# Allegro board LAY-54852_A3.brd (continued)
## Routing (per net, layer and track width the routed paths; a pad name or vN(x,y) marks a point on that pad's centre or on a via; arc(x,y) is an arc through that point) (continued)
VRPI_3V3: length 26.4
  TOP w0.508: J1401.17 v1(108.51,73.84)
  BOTTOM w0.508: v1(86.85,77.34) 88.83,75.36 102.11,75.36 103.97,73.5 104.46,73.5 104.91,73.05 107.94,73.05 108.51,73.62 v1(108.51,73.84)
VSD2_3V3: length 40.7
  TOP w0.254: U1708.A1 130.26,43.85 D1003.1
  TOP w0.508: J1002.4 125.06,53.99 C1732.1 122.54,53.99 R1055.2 v1(122.37,54.88) ; v1(122.37,44.17) 120.29,42.08 120.29,38.83 122.58,36.54 125.57,36.54 TP1919.1 129.56,40.53 C1731.1 130.24,42.84 131.73,42.84 132.21,43.32 D1003.1
  BOTTOM w0.508: v1(122.37,54.88) 123.04,54.21 123.04,44.84 v1(122.37,44.17)
VSD_3V3: length 108.5
  TOP w0.203: v1(65.94,26.23) 65.71,26.47 U701.23
  TOP w0.254: U1708.A2 127.83,44.2 C1020.1
  TOP w0.381: v1(67.2,21.11) 67.2,24.97 v1(65.94,26.23)
  TOP w0.508: v1(118.9,45.52) 115.69,48.73 v1(108.03,48.73) ; v1(75.99,24.77) 75.36,24.14 75.36,20.52 v1(74.69,19.85) ; R1055.1 v1(120.25,54.16) ; v1(121.19,45.52) 126.91,45.52 127.71,44.72 C1020.1
  BOTTOM w0.381: C725.1 65.74,26.44 v1(65.94,26.23)
  BOTTOM w0.508: v1(118.9,45.52) v1(121.19,45.52) 121.46,45.79 121.46,52.94 v1(120.25,54.16) ; v1(67.2,21.11) 67.2,20.07 68.4,18.88 73.72,18.88 v1(74.69,19.85) ; v1(108.03,48.73) 108.51,48.73 110.88,46.36 110.88,38.14 108.27,35.52 101.75,35.52 95.25,29.02 94.44,29.02 92.96,27.54 92.96,26.98 91,25.03 76.25,25.03 v1(75.99,24.77)
VSYS_5V: length 69.7
  TOP w0.203: v1(63.55,35.12) 63.71,34.95 U701.53
  TOP w0.254: U701.56 61.66,34 v1(61.53,34.13) ; R906.1 42.66,34.97 42.51,34.82 U901.5
  TOP w0.381: R906.1 43.38,34.93 C902.1 v1(42.6,33.94)
  TOP w0.457: 134.97,28.91 131.96,28.91 R1783.1
  BOTTOM w0.381: v1(43.59,40.97) 42.6,39.98 v1(42.6,33.94)
  BOTTOM w1.27: 136.57,27.94 136.57,22.5 137.21,21.86 137.21,7.31 132.68,2.78 108.96,2.78
  vias: v1(32.01,21.94) v1(32.02,21.39) v1(32.03,20.87) v1(32.03,20.36) v1(37.33,43.99) v1(37.35,43.36) v1(37.96,43.99) v1(38,43.46) v1(56.76,38.78) v1(56.74,38.27) v1(56.91,41.01) v1(56.93,40.38) v1(57.54,41.01) v1(57.57,40.48) v1(63.01,26.23) v1(63.64,26.21) v1(65.36,34.98) v1(65.99,34.96) v1(69.53,30.3) v1(69.51,29.67) v1(107.58,3.58) v1(107.58,3.07) v1(107.58,2.48) v1(107.6,1.97) v1(136.47,30.07) v1(136.47,29.49) v1(136.49,28.92)
VTREF: length 2.9
  TOP w0.091: R1454.2 30.75,51.01 J1704.1
WDOG_B: length 224.3
  TOP w0.081: U101.H14 v1(90.99,52.71)
  TOP w0.091: v1(97.02,62.13) 97.02,62.6 95.58,64.04 95.58,65.2 91.5,69.28 70.46,69.28 70.14,69.59 60.98,69.59 57.9,72.68 v1(48.16,72.68) ; v1(54.62,58.47) 38.16,58.47 33.04,63.59 v1(33.04,63.97) ; v1(74.7,22.64) 74.78,22.72 74.78,23.41 TP916.1 73.23,23.62 R710.1 ; v1(31.99,57.06) 31.71,56.78 26.42,56.78 23.33,53.69 23.33,51.53 21.92,50.12 18.19,50.12 16.12,52.18 16.12,53.96 11.32,58.76 11.32,59.32 9.71,60.93 Q1407.1 9,62.38 7.34,62.38 6.72,61.76 Q1411.1 ; v1(42.91,72.68) 34.23,72.68 v1(33.41,71.85)
  BOTTOM w0.091: v1(31.99,57.06) 31.99,57.08 33.04,58.13 v1(33.04,63.97) 33.04,71.48 v1(33.41,71.85) ; v1(42.91,72.68) v1(48.16,72.68) ; v1(97.02,62.13) 96.4,61.51 96.4,57.01 95.77,56.38 95.77,55.42 92.11,51.75 91.95,51.75 v1(90.99,52.71) ; v1(54.62,58.47) 54.66,58.43 54.66,31.66 55.3,31.02 55.3,19.29 55.95,18.65 63.61,18.65 66.97,22 68,22 68.16,21.84 69.59,21.84 70.04,22.29 74.35,22.29 v1(74.7,22.64)
XIN_32K: length 6.2
  TOP w0.091: QZ701.2 58.51,28.21 58.81,28.51 C716.1
  TOP w0.104: U701.10 61.01,29.55 59.84,28.38 59.84,27.92 59.74,27.82 R720.1 59.34,28.51 C716.1
XOUT_32K: length 6.5
  TOP w0.104: QZ701.1 57.7,25.71 58.56,26.57 C717.1 59.34,27.28 R720.2 59.57,27.28 60.07,27.78 60.07,28.19 61.04,29.15 U701.11
XTALI_24M: length 14.3
  TOP w0.081: U101.A9 88.49,57.31 88.65,57.46 88.65,57.85 v1(88.51,57.99)
  TOP w0.091: v1(88.56,65.32) 88.56,65.32 88.17,65.7 87.75,65.7 TP410.1
  BOTTOM w0.081: 88.85,58.37 88.76,58.37 88.51,58.13 v1(88.51,57.99)
  BOTTOM w0.091: 91.04,62.68 90.03,63.7 90.03,64.89 89.86,65.06 88.82,65.06 v1(88.56,65.32) 88.46,65.42 R409.1 89.29,65.91 C404.1 ; 91.04,62.68 Y401.1 ; 91.04,62.68 91.01,62.68 90.24,61.92 90.24,61.74 89.42,60.92 89.42,58.95 88.85,58.37
XTALI_32K: length 7.2
  TOP w0.091: v1(86.53,57.28) 86.55,57.26 86.55,56.76 U101.A5
  BOTTOM w0.081: 86.85,58.1 86.85,57.6 v1(86.53,57.28)
  BOTTOM w0.102: R407.1 86.69,60.51 86.85,60.35 86.85,58.1 ; R407.1 86.69,62.47 R406.2 ; R407.1 86.71,62.04 TP407.1
XTALO_24M: length 12.4
  TOP w0.081: 88.39,58.37 88.17,58.16 88.17,57.63 88.25,57.55 88.25,56.45 U101.B9
  TOP w0.091: 88.39,58.37 88.48,58.46 88.48,58.59 v1(88.46,58.6)
  BOTTOM w0.091: C405.1 87.69,65.93 R409.2 87.71,65.51 Y401.3 89.91,63.32 89.91,61.72 89.18,60.99 89.18,59.04 88.74,58.6 v1(88.46,58.6)
XTALO_32K: length 10.6
  TOP w0.081: U101.B5 86.25,56.45 86.25,56.91
  TOP w0.091: 86.25,56.91 86.14,57.03 86.14,57.39 v1(86.53,57.78)
  TOP w0.102: R408.2 v1(83.98,62.08)
  BOTTOM w0.081: 86.34,58.37 86.53,58.18 v1(86.53,57.78)
  BOTTOM w0.091: v1(83.98,62.08) 83.98,60.73 86.34,58.37
  BOTTOM w0.102: v1(83.98,62.08) 83.42,62.08 C403.1 83.4,62.69 82.8,63.29 QZ401.1
N111682856: length 5.1
  TOP w0.254: S1501.2 39.39,62.19 C1507.1 39.39,65.34 38.75,65.97 R1504.1
N111682880: length 1.7
  TOP w0.381: R1505.1 24.88,77.8 D1501.C
N111682886: length 1.3
  TOP w0.254: R1506.1 33.82,77.8 D1502.C
N111683153: length 4.3
  TOP w0.254: R1511.2 45.87,64.97 C1508.1 44.69,63.14 S1501.1
N111686445: length 4.6
  TOP w0.254: R901.1 38.99,35.77 U901.8
N111686449: length 1
  TOP w0.254: C901.1 35.94,41.09 R901.2
N111686641: length 33.2
  TOP w0.381: R907.1 35.81,31.9 36.62,31.1 37.33,31.1 38.84,29.59 38.84,22.44 38.95,22.33
  TOP w0.508: D901.C 47.32,7.64 43.52,11.43 43.52,18.98 42.04,20.46 40.81,20.46 38.95,22.33
N111686683: length 2.1
  TOP w0.305: R907.2 37.97,33.82 U901.12
N111686689: length 16.1
  TOP w0.254: R906.2 44.71,34.97 44.96,34.72 44.96,31.58 44.71,31.32 42.82,31.32 v1(42.46,30.97) ; v1(36.54,33.27) 36.66,33.38 R910.1
  TOP w0.305: U901.11 36.73,34.32 R910.1
  BOTTOM w0.254: v1(36.54,33.27) 38.84,30.97 v1(42.46,30.97)
N111686749: length 10.3
  TOP w0.254: R911.1 42.76,36.12 41.97,35.32 U901.6 40.94,36 v1(41,36.06) ; R908.2 v1(35.75,37.55)
  BOTTOM w0.254: v1(35.75,37.55) 39.51,37.55 v1(41,36.06)
N112168459: length 4.2
  TOP w0.091: U1401.12 118.91,67.73 118.42,68.22 118.42,69.66 117.43,70.65 R1402.2
N112168530: length 2.9
  TOP w0.091: U1401.11 119.77,70.04 TP1402.1
N112168572: length 2.3
  TOP w0.091: R1409.2 119.77,64.44 U1401.1
N112168574: length 2.8
  TOP w0.091: U1401.10 120.27,70.4 TP1403.1
N112168590: length 2.2
  TOP w0.091: U1401.2 120.27,64.4 R1410.2
N112168603: length 2.5
  TOP w0.091: R1412.2 120.77,65.12 U1401.3
N112168605: length 3.5
  TOP w0.091: TP1404.1 120.77,69.08 U1401.9
N112168607: length 5.1
  TOP w0.091: D1401.C 124.03,64.87 R1420.2 121.27,65.81 U1401.4
N112179037: length 9.9
  TOP w0.091: J1401.37 133.91,74.38 133.3,73.77 v1(131.46,73.77)
  L3_PWR w0.114: J1710.2 128.35,72.21 129.91,73.77 v1(131.46,73.77)
N112179124: length 3.1
  TOP w0.091: J1401.36 v1(131.37,83.77)
  BOTTOM w0.091: v1(131.37,83.77) 131.27,83.67 R856.1
N112179125: length 37.2
  TOP w0.091: v1(130.04,78.99) 130.04,83.4 128.86,84.58 102.36,84.58 100.89,83.11 J1401.12
  BOTTOM w0.091: R855.1 130.06,78.97 v1(130.04,78.99)
N112179128: length 2.8
  TOP w0.091: J1401.16 v1(105.97,79.17)
  BOTTOM w0.091: v1(105.97,79.17) 105.96,79.18 R853.1
N112247759: length 6.5
  TOP w0.091: R811.2 104.84,65.5 C803.1 104.97,64.48 R804.2 105.38,63.81 105.38,62.36 105.92,61.82 U801.28
N112248110: length 5.2
  TOP w0.091: U801.32 106.76,59.82 105.48,58.54 105.48,57.58 R813.2 104.82,56.92 R823.2
N112248290: length 4.7
  TOP w0.091: R830.2 R824.2 R801.2 105.52,60.82 U801.30
N112248296: length 4.5
  TOP w0.091: R820.2 R828.2 R802.2 105.85,61.19 105.98,61.32 U801.29
N113364863: length 9.5
  TOP w0.091: R1444.1 59.68,65.66 J1405.6 54.45,65.66 54.16,65.37 54.16,63.97 54.48,63.65 J1405.8
N113365543: length 4.1
  TOP w0.091: J1405.3 49.23,67.69 R1446.1 49.13,68.9 R1440.2
N113365548: length 4.3
  TOP w0.091: R1441.2 49.15,65.48 R1447.1 50.13,65.46 50.33,65.66 J1405.5
N113409056: length 5.8
  TOP w0.091: R1426.1 22.77,82.34 SW1401.3 SW1401.4
N113409060: length 6.3
  TOP w0.091: R1427.1 36.66,81.72 36.04,82.34 SW1402.4 SW1402.3
N113524078: length 3.7
  TOP w0.102: R408.1 86.04,61.8 v1(86.04,61.53)
  BOTTOM w0.102: v1(86.04,61.53) 86.16,61.64 R407.2 85.54,62.06 C402.1 85.53,62.52 85.3,62.75 QZ401.2
N113527145: length 6.4
  TOP w0.104: U701.38 69.26,31.55 69.88,32.17 69.88,33.61 70.29,34.02 R701.2 R711.1
N113527381: length 5.1
  TOP w0.203: R718.1 R716.2 71.05,27.15 70.31,27.15 69.85,27.61 69.85,27.83 69.32,28.35 U701.30
N113528020: length 6.1
  TOP w0.104: U701.12 61.15,28.75 60.37,27.98 60.37,27.67 ; 59.67,25.46 58.68,24.47 R723.1
  TOP w0.109: 59.67,25.46 59.67,26.98 60.37,27.67
N113528254: length 5.3
  TOP w0.203: C728.1 60.65,33.3 61.19,32.75 U701.2
  TOP w0.254: C728.1 59.82,33.55 59.56,33.81 58.6,33.81 57.73,34.68 TP710.1
N113528336: length 3.7
  TOP w0.203: U701.1 61.39,33.15 60.86,33.68
  TOP w0.381: 60.86,33.68 60.78,33.76 60.78,34.56 60.64,34.7 ; 60.64,34.7 v1(60.67,34.72) ; 60.64,34.7 60.3,34.7 C730.1
  BOTTOM w0.381: v1(60.67,34.72) 60.16,35.23 R871.1
N114502549: length 1.6
  TOP w0.091: R1703.2 22.68,72 U1702.2
N114502556: length 2
  TOP w0.091: R1704.2 24.37,70.29 U1702.5
N114502597: length 2.1
  TOP w0.091: U1702.7 25.17,69.57 24.67,69.07 R1705.2
N114579559: length 2.6
  TOP w0.091: U801.1 107.93,58.72 107.62,58.41 106.83,58.41 R805.1
N114579565: length 2.1
  TOP w0.091: R807.1 107.55,58.12 107.92,58.12 108.43,58.63 U801.2
N114579571: length 1.7
  TOP w0.091: U801.3 108.93,58.47 R806.1
N114579577: length 1.5
  TOP w0.091: U801.4 109.43,58.56 109.14,58.28 R809.1
N114579583: length 1.4
  TOP w0.091: U801.5 109.93,57.91 R812.1
N114579589: length 1.7
  TOP w0.091: U801.6 110.43,58.42 R810.1
N114579595: length 25.9
  TOP w0.091: U801.7 110.93,58.64 111.4,58.17 112.84,58.17 v1(113.29,58.61)
  BOTTOM w0.091: v1(113.29,58.61) 113.29,58.66 114.4,59.78 114.4,73.42 113.12,74.7 113.12,78.17 114.58,79.63 R850.1
N114579601: length 24.9
  TOP w0.091: v1(113.24,59.14) 113.12,59.02 U801.8
  BOTTOM w0.091: v1(113.24,59.14) 114.19,60.09 114.19,72.99 109.49,77.68 R851.1
N114598355: length 1.8
  TOP w0.091: v1(113.24,59.68) 113.13,59.68 112.99,59.82 U801.9
  BOTTOM w0.091: v1(113.24,59.68) 113.32,59.68 113.46,59.82 R852.1
N114598565: length 2.5
  TOP w0.091: U801.10 113.28,60.32 114.14,59.46 R845.1
N114629076: length 3.1
  TOP w0.254: R703.2 R706.2 60.42,29.93 60.84,30.35 U701.8
N114629170: length 6.2
  TOP w0.112: R710.2 72.65,24.38 R705.2 71.34,24.63 68.87,27.1 U701.28
N114629402: length 2.2
  TOP w0.091: R818.1 113.48,60.82 U801.11
N114629754: length 6.1
  TOP w0.104: R707.2 69.65,33.78 69.65,32.27 69.33,31.95 U701.39
N114629773: length 6.7
  TOP w0.104: U701.40 69.31,32.35 69.42,32.46 69.42,33.89 71.54,36.02 71.54,36.73 R708.2
N114629886: length 7.6
  TOP w0.104: U701.42 68.56,33.78 70.99,36.2 70.99,38.3 R715.2
N114629887: length 7.2
  TOP w0.104: R714.2 71.26,37.51 71.26,36.12 69.19,34.05 69.19,32.86 69.08,32.75 U701.41
N114636326: length 4.3
  TOP w0.203: TP714.1 58.06,32.07 58.31,31.82 59.86,31.82 60.46,31.22 61.06,31.22 61.13,31.15 U701.6
N114797754: length 2
  TOP w0.091: R1423.1 82.02,75.06 81.03,76.05 D1402.4
N114797756: length 1.9
  TOP w0.091: R1424.1 81.03,81.09 D1402.3
N114797758: length 2.8
  TOP w0.091: D1402.1 79.53,75.16 79.87,74.82 R1425.1
N114798676: length 3.5
  TOP w0.091: R1439.2 76.75,73.86 R1435.1 78.25,72.35 Q1403.1
N114798680: length 2.8
  TOP w0.091: R1438.2 R1434.1 74.52,84.64 Q1401.1
N114800112: length 2.8
  TOP w0.091: R1429.2 87.7,72.76 R1433.1 86.01,72.22 Q1402.1
N114994571: length 3.2
  TOP w0.254: 50.81,38.18 U902.5
  TOP w0.381: R912.2 48.82,37.46 49.55,38.18 50.81,38.18
N114994603: length 2.8
  TOP w0.254: U902.2 52.01,41.12 52.07,41.19 R915.2 52.08,41.6 R213.2
N114997192: length 2.1
  TOP w0.254: R913.1 50.41,36.68 51.51,37.78 U902.6
N114999418: length 1.2
  TOP w0.381: D902.A R914.2
N115302368: length 2.4
  TOP w0.091: R839.1 129.44,69.39 130.14,70.09 U803.13
N115329910: length 3
  TOP w0.091: R854.2 105.97,73.43 J1401.15
N115331791: length 9.6
  TOP w0.091: J1405.2 54.5,69.7 54.24,69.44 54.24,67.95 54.5,67.69 J1405.4 58.43,67.69 59.31,66.82 R1442.1
N115508226: length 1.9
  TOP w0.091: U804.13 102.83,70.93 103.25,70.51 R841.1
N115508248: length 2.1
  TOP w0.102: U805.13 113.37,70.41 R840.1
N115511669: length 2.5
  TOP w0.091: U801.18 110.93,65.05 R829.1
N115511689: length 2.3
  TOP w0.091: U801.19 110.43,65.57 R833.1
N115511709: length 2.1
  TOP w0.091: R832.1 109.93,66.08 U801.20
N115511729: length 2.2
  TOP w0.091: R835.1 109.43,65.74 U801.21
N115511749: length 2.4
  TOP w0.091: R858.1 108.93,65.21 U801.22
N115511769: length 2.7
  TOP w0.091: R836.1 106.97,65.92 108.43,64.46 U801.23
N115511789: length 3
  TOP w0.091: R837.1 106.15,66.17 107.93,64.39 U801.24
N115511922: length 2.1
  TOP w0.091: U801.13 113.74,61.82 R821.1
N115511942: length 2.3
  TOP w0.091: U801.14 113.22,62.32 R825.1
N115511962: length 4.2
  TOP w0.091: v1(114.9,64.58) 114.45,64.13 114.25,64.13 112.95,62.82 U801.15
  BOTTOM w0.091: v1(114.9,64.58) 115.02,64.47 R860.1
N115511982: length 2.9
  TOP w0.091: R826.1 112.98,64.11 112.98,63.79 112.51,63.32 U801.16
N115512059: length 2.7
  TOP w0.091: R831.1 111.43,64.53 U801.17
N115512397: length 1.9
  TOP w0.091: U801.12 113.26,61.32 113.39,61.19 R822.1
N115575393: length 5.1
  TOP w0.091: U101.A3 85.49,57.39 85.05,57.84 85.05,60.42 84.44,61.03 R303.1
N115646354: length 3.9
  TOP w0.508: D1704.A 3.62,12.34 U1410.5 v1(6.09,12.34)
  BOTTOM w0.381: C1727.1 5.82,12.08 v1(6.09,12.34)
N115646421: length 5.4
  TOP w0.254: U1706.9 11.5,20.11 C1729.1
  TOP w0.508: L1703.2 11.95,17.01 C1728.1 11.95,19.62 C1729.1
N115646547: length 1.9
  TOP w0.381: U1410.4 v1(6.29,14.24)
  BOTTOM w0.381: C1730.1 5.82,14.24 v1(6.29,14.24)
N115646842: length 5.5
  TOP w0.254: U1706.4 9,19.85 C1416.1
  TOP w0.508: L1704.2 9.61,17.64 C1415.1 8.76,18.5 C1416.1
N115647748: length 3.7
  TOP w0.091: TP1429.1 20.53,30.06 18.48,30.06 18.28,29.87 U1706.29
N115647777: length 4.4
  TOP w0.091: TP1951.1 17.03,34.78 U1706.32
N115647791: length 4.1
  TOP w0.091: U1706.33 15,34.96 TP1952.1
N115647810: length 3.7
  TOP w0.091: TP1413.1 14.5,35.79 U1706.34
N115647904: length 1
  TOP w0.091: R1729.1 12.58,40.9 D1403.A
N115647959: length 1.5
  TOP w0.091: R1730.1 6.95,40.32 D1404.A
N115647999: length 3.7
  TOP w0.091: U1706.40 11.5,35.81 TP1414.1
N115648034: length 3.4
  TOP w0.091: TP1415.1 11,36.53 U1706.41
N115648083: length 3.5
  TOP w0.091: TP1416.1 9.78,36.44 9.78,34.62 10,34.39 U1706.43
N115648105: length 3.8
  TOP w0.091: TP1417.1 9.5,35.49 U1706.44
N115648131: length 4.1
  TOP w0.091: U1706.45 9,34.77 TP1418.1
N115648181: length 4.9
  TOP w0.091: TP1419.1 6.56,36 7.47,36 8.5,34.96 U1706.46
N115648263: length 1
  TOP w0.091: D1406.A 9.73,40.95 R1421.1
N115648354: length 1.7
  TOP w0.381: D1405.A 3.76,53.36 4.41,52.71 4.41,51.96 R1733.1
N115648363: length 4
  TOP w0.091: U1706.14 14,21.02 C1431.1 15.6,19.43 R1737.2
N115648415: length 2.3
  TOP w0.091: U1706.6 10,19.6 R1738.1
N115648419: length 3.8
  TOP w0.091: U1706.55 3.03,28.37 TP1420.1
N115648439: length 3.1
  TOP w0.091: U1405.1 4.67,46.16 R1422.1 5.86,46.3 R1734.2
N115648441: length 5.9
  TOP w0.091: R1735.2 R1428.1 ; R1735.2 2.97,40.14 3.14,39.97 3.14,38.14 TP1431.1 ; R1735.2 2.62,40.9 2.77,41.05 U1405.4
N115648443: length 6
  TOP w0.091: R1736.2 R1740.1 ; R1736.2 3.82,41.66 U1405.5 ; R1736.2 3.48,40.14 3.39,40.04 3.39,38.23 TP1432.1
N115648445: length 3.9
  TOP w0.091: U1706.57 3.25,27.37 TP1421.1
N115648473: length 4.2
  TOP w0.091: U1706.58 3.97,26.87 TP1422.1
N115648499: length 4.4
  TOP w0.091: TP1423.1 4.69,26.37 U1706.59
N115648584: length 5.6
  TOP w0.091: U1405.3 2.77,46.29 R1739.1 3.99,46.31 4.73,47.05 R1422.2 4.81,47.07 TP1430.1
N115648905: length 1.8
  TOP w0.091: U1406.7 13.47,61.29 R1430.1
N115648976: length 2.2
  TOP w0.091: R1741.1 14.62,62.29 U1406.5
N115649042: length 1.7
  TOP w0.091: U1406.2 19.74,61.29 R1743.1
N115649073: length 4.2
  TOP w0.254: 14.97,67.06 R1742.2 14.95,65.09 R1744.2 ; 14.97,67.06 14.88,66.97 U1407.1 ; 14.97,67.06 Q1404.3
N115649242: length 2.6
  TOP w0.381: R1467.2 4.56,64.18 3.75,64.18 D1412.A
N115649244: length 4
  TOP w0.152: D1413.A 4.26,66.13 5.37,67.25 5.37,68.49 R1748.2
N115649263: length 2.5
  TOP w0.254: R1750.1 18.3,66.45 R1749.2 16.92,66.45 Q1404.1
N115649426: length 1.1
  TOP w0.254: R1464.2 4.78,49.94 D1411.A
N115649428: length 2
  TOP w0.254: R1465.2 5.65,56.33 3.75,56.33 D1410.A
N115649511: length 5.4
  TOP w0.254: R1751.2 13.66,70.46 R1753.1 13.64,69.33 R1755.1 14.17,69.33 14.56,68.94 14.56,67.92 14.11,67.47 U1407.2
N115649521: length 9.6
  TOP w0.091: R1755.2 11.69,69.33 10.28,67.93 8.13,67.93 7.78,68.28 6.06,68.28 5.8,68.03 R1752.1
  TOP w0.254: U1407.4 12.89,68.19 12.84,68.25 12.84,68.75 12.89,68.81 R1755.2
N115650186: length 2.6
  TOP w0.091: R1486.2 R1487.2 21.46,53.21 U1409.22
N115650188: length 3.3
  TOP w0.091: R1490.1 17.05,56.33 R1485.2 17.06,55.25 U1409.18
N115650272: length 1.7
  TOP w0.091: U1409.5 24.73,57.25 TP1424.1
N115650294: length 2
  TOP w0.091: TP1425.1 24.01,57.75 U1409.6
N115650321: length 2.9
  TOP w0.091: TP1426.1 24.21,59.16 23.45,59.16 22.74,58.46 U1409.7
N115650337: length 3.6
  TOP w0.091: Q1406.3 30.97,54.17 R1454.1 30.89,52.16 C1449.1
N115650366: length 2.3
  TOP w0.091: U1409.8 21.96,58.91 22.85,59.8 TP1427.1
N115650410: length 18.5
  TOP w0.091: v1(29.9,50.84) 29.9,51.32 C1449.2 29.29,51.42 29.07,51.63 29.07,51.86 28.77,52.16 R1449.1 28.42,52.74 28.57,52.89 29.22,52.89 29.7,53.37 29.7,54.83 29.39,55.13 Q1406.1 27.8,55.13 R1756.2 ; C1448.2 v1(31.87,42.32)
  BOTTOM w0.091: v1(31.87,42.32) 31.87,48.86 v1(29.9,50.84)
N115650590: length 3.6
  TOP w0.091: TP1428.1 17.51,56.89 17.51,56.16 17.92,55.75 U1409.17
N115650809: length 2.3
  TOP w0.091: R1450.2 10.32,64.86 R1455.2 10.32,63.62 Q1407.3
N115650811: length 2.5
  TOP w0.091: R1457.2 23.79,63.92 R1451.2 22.69,64.92 Q1408.3
N115650813: length 3.5
  TOP w0.091: Q1409.3 19.64,19.68 R1452.2 18.59,21.24 R1456.2
N115650815: length 1
  TOP w0.254: D1415.A 3.76,58.97 R1453.2
N115650891: length 2.8
  TOP w0.091: R1461.1 24.01,41.03 D1407.C
N115651044: length 9.1
  TOP w0.254: D1415.C 3.27,60.03 6.13,60.03 R1458.2
  TOP w0.305: R1458.2 6.71,59.94 Q1410.3 9.96,59.94 R1816.2
N115651255: length 4.9
  TOP w0.254: R1468.2 4.84,62.91 5.52,63.58 Q1411.3
  TOP w0.381: R1468.2 4.79,61.88 3.75,61.88 D1414.A
N115651302: length 3.2
  TOP w0.091: R1462.1 26.94,50.92 J1704.7
N115651381: length 3.2
  TOP w0.091: J1704.9 25.67,51.01 R1463.1
N115688375: length 9.4
  TOP w0.091: R1057.2 136.39,46.12 130.1,46.12 129.42,45.45 U1708.B2
N115740207: length 35.6
  TOP w0.091: R1758.2 49.71,22.04 R305.2 49.2,22.05 v1(49.1,21.95) 48.72,21.95 U302.A3 ; Q301.3 73.48,17.02 v1(73.41,16.94)
  BOTTOM w0.091: v1(49.1,21.95) 49.1,21.59 57.99,12.7 71.88,12.7 73.41,14.23 v1(73.41,16.94)
N115740283: length 2.9
  TOP w0.254: SW301.3 70.04,5.95 R358.2 R353.2
N115740287: length 2.7
  TOP w0.254: R352.1 R356.1 69.71,3.78 SW301.2
N115740320: length 3
  TOP w0.254: R354.2 R359.2 65.8,6.99 SW301.6
N115740338: length 3.2
  TOP w0.254: SW301.5 65.64,3.35 R357.1 R355.1
N115740452: length 8.7
  TOP w0.254: R1760.2 71.39,17.54 R1761.1 71.9,17.54 72.27,17.17 72.27,15.54 71.94,15.22 C304.1 72.7,14.4 Q301.1 74.44,14.1 D301.A
N115740524: length 1.1
  TOP w0.091: TP305.1 70.65,11.76 U303.C3
N115740681: length 27.3
  TOP w0.091: R1764.2 67.72,9.04 64.16,9.04 62.15,11.05 62.15,14.17 v1(61.68,14.64) ; Q302.3 52.37,22.92 R1762.2 v1(51.7,21.71)
  BOTTOM w0.091: v1(51.7,21.71) 52.13,21.29 52.13,20.26 57.74,14.64 v1(61.68,14.64)
N115740897: length 1.8
  TOP w0.091: R313.1 66.82,15.09 67.21,15.09 67.44,14.86 U301.5
N115742694: length 3.3
  TOP w0.305: R1766.2 24.87,36.38 25.08,36.16 25.08,35.99 25.41,35.65 R1772.1 25.76,35.13 25.58,34.95 U404.4
N115742746: length 5.2
  TOP w0.305: D302.C 27.96,30.27 R360.2 27.84,29.98 R1769.2 26.93,29.99 R1771.1 25.86,30.59 25.58,30.87 U404.3
N115743253: length 2.7
  TOP w0.203: C407.1 23.66,13.9 U402.A6
N115743279: length 2
  TOP w0.091: C409.1 26.85,15.5 26.71,15.64 U402.A3
N115743338: length 2.3
  TOP w0.091: U402.A2 27.11,15.21 28.03,14.29 R412.2
N115743354: length 7.7
  TOP w0.091: U402.E1 29.13,17.35 29.33,17.15 R413.2 30.32,16.82 30.41,16.73 31.88,16.73 32.25,16.36 32.25,15.43 31.77,14.95 R434.2
N115743625: length 8.2
  TOP w0.381: D402.C 29.34,28.99 D401.C 29.4,32.82 C414.1 29.69,34.71 U405.2
N115744998: length 1.4
  TOP w0.091: U411.C3 34.34,20.46 TP1932.1
N115747363: length 2.2
  TOP w0.091: U1712.14 92.57,30.62 92.95,30.99 R1780.2
N115747381: length 2.2
  TOP w0.091: R503.2 92.95,29.85 92.57,30.22 U1712.13
N115751791:
  vias: v1(133.55,34.42) v1(134.06,34.42) v1(134.57,34.42)
N115751937: length 5
  TOP w0.254: U1710.3 132.04,34.85 131.22,35.68 C1749.2 131.2,36.37 R902.2 128.88,36.37 R1782.1
N115752033: length 2
  TOP w0.091: U1710.6 131.19,31.25 R1783.2
N115752037: length 2.7
  TOP w0.254: C1753.1 130.53,33.7 U1710.4
N115752085: length 1.8
  TOP w0.091: U1710.7 132.04,31.28 132.09,31.23 TP901.1
N115752389: length 1.8
  TOP w0.091: U904.2 128.87,26.02 R1784.2
N115752394: length 3.4
  TOP w0.091: R946.1 130.91,22.17 130.33,22.74 129.48,22.74 128.87,23.36 U904.10
N115752439: length 1.5
  TOP w0.091: U904.3 128.47,26.72 R1785.2
N115752462: length 2.8
  TOP w0.091: U904.9 128.47,23.25 129.19,22.52 129.73,22.52 R947.1
N115752527: length 1.8
  TOP w0.091: R1786.2 128.07,26.16 U904.4
N115752535: length 2.2
  TOP w0.091: U904.8 128.07,23.11 R948.1
N115752568: length 2
  TOP w0.091: U904.5 127.67,25.47 R909.2
N115752570: length 1.9
  TOP w0.091: U904.7 127.67,22.46 R949.1
N115753009: length 1.8
  TOP w0.091: D1705.A 133.46,19.29 133.8,19.64 R1790.1
N115753214: length 1
  TOP w0.091: D1706.A 131.14,18.34 R1791.1
N115753489: length 3.8
  TOP w0.091: Q901.3 119.94,21.25 120.38,20.81 120.47,20.81 120.88,20.4 R918.2 120.07,19.16 120.06,19.14 R919.2
N115753655: length 3
  TOP w0.381: R958.1 121.04,23.39 120.9,23.24 Q901.1 120.59,24.65 R959.1
N115753665: length 5.4
  TOP w0.091: J1707.62 118.1,15.38 116.17,17.32 R932.1
N115754842: length 3
  TOP w0.091: R1448.1 49.17,63.65 J1405.7
N115756645: length 17.2
  TOP w0.076: 104.27,29.07 104.27,28.58 U1709.E3
  TOP w0.081: 104.27,29.07 104.27,30.11 103.85,30.54 103.85,30.71
  TOP w0.091: v1(103.85,33.54) 103.85,30.71 ; R1204.2 v1(113.42,37.05)
  BOTTOM w0.091: v1(113.42,37.05) 113.15,37.05 109.63,33.54 v1(103.85,33.54)
N115756807: length 2
  TOP w0.203: U1709.G7 102.31,29.54 102.31,30.68 R1209.2
N115757278: length 2.4
  TOP w0.091: U1202.4 113.41,32.23 R1222.1 113.42,33.28 R1219.2
N115782425: length 5.5
  TOP w0.254: U1306.5 11.88,75.39 C1323.1
  TOP w0.305: R1814.1 10.83,73.24 C1321.1 ; C1321.1 10.89,73.21 C1322.1 11.88,73.23 C1323.1 ; C1321.1 R1329.1
N115782532: length 4.4
  TOP w0.254: U1306.4 9.07,75.41 8.69,75.03 R1330.1 R1329.2 C1321.2
N115782544: length 1.6
  TOP w0.254: R1333.2 9.86,78.13 U1306.3
N115782790: length 2.8
  TOP w0.091: R1302.1 2.75,5.86 3.89,6.99 U1301.1
N115782792: length 169.1
  TOP w0.091: v1(73,1.73) 73.06,1.67 R1303.2 ; U1307.2 18.77,78.58 16.88,80.47 14.36,80.47 v1(12.47,82.36) ; R1302.2 2.38,6.61 v1(2.44,6.55)
  BOTTOM w0.091: v1(12.47,82.36) 7.19,77.08 7.19,70.9 2.86,66.57 2.86,26.09 5.54,23.41 5.54,15.73 2.86,13.05 2.86,7.81 2.34,7.28 2.34,6.66 v1(2.44,6.55) 2.85,6.15 5.11,6.15 8.43,2.83 52.66,2.83 53.87,4.04 63.17,4.04 64.57,2.65 72.08,2.65 v1(73,1.73)
N115782811: length 243.2
  TOP w0.091: R1327.1 71.69,79.97 71.21,80.46 71.21,82.92 69.39,84.74 22.85,84.74 v1(22.04,83.93) 21.88,83.77 4.07,83.77 1.47,81.17 1.47,79.84 1.69,79.62 R1326.1 2.45,79.62 v1(2.46,79.62) ; R1324.1 1.67,9.67 v1(2.03,10.03) 2.9,10.9 3.71,10.9 v1(3.75,10.86) ; R1325.1 v1(76.67,12.29) ; v1(21.33,81.67) 20.81,81.15 U1309.4
  BOTTOM w0.091: v1(21.33,81.67) 21.33,83.22 v1(22.04,83.93) ; v1(76.67,12.29) 74.19,9.82 74.19,8.28 70.77,4.86 49.51,4.86 48.29,6.08 36.73,6.08 34.28,3.64 11.5,3.64 8.23,6.91 5.87,6.91 3.75,9.03 v1(3.75,10.86) ; v1(2.03,10.03) 2.64,10.64 2.64,13.14 5.28,15.78 5.28,22.76 2.64,25.4 2.64,67.31 6.35,71.02 6.35,73.41 3.24,76.51 3.24,78.91 2.53,79.62 v1(2.46,79.62)
N115782815: length 3
  TOP w0.091: U1301.2 3.89,8.83 3.34,9.37 2.64,9.37 1.76,8.5 R1324.2
N115783013: length 5.1
  TOP w0.091: R1303.1 74,6.28 74.73,7.01 U1302.1
N115783041: length 4.5
  TOP w0.091: R1325.2 75.92,10.82 75.29,10.19 74.37,10.19 74.24,10.06 74.24,9.42 74.73,8.94 U1302.2
N115783217: length 2.5
  TOP w0.091: U1304.1 3.89,77.77 3.52,77.4 R1318.1
N115783219: length 106.4
  TOP w0.091: v1(2.15,81.12) 2.08,81.19 2.08,81.35 4.2,83.47 22.15,83.47 23.05,84.37 69.31,84.37 70.93,82.75 70.93,78.07 71.99,77.01 R1322.2 ; U1308.2 19.3,69.22 19.09,69 17.43,69 17.13,69.31 17.13,70.49 16.45,71.17 8.61,71.17 7.93,71.85 7.85,71.85 4.19,75.51 v1(1.9,75.51) 1.9,75.51 R1318.2
  BOTTOM w0.091: v1(2.15,81.12) 1.9,80.87 v1(1.9,75.51)
N115783240: length 2.5
  TOP w0.091: U1304.2 3.89,79.66 3.17,80.37 R1326.2
N115783428: length 2.9
  TOP w0.091: U1305.1 74.73,77.82 74.16,77.26 73.43,77.26 72.92,77.76 R1322.1
N115783445: length 2.9
  TOP w0.254: R1327.2 73.67,80.72 74.73,79.66 U1305.2
N115785368: length 2.2
  TOP w0.091: R601.2 43.75,54.94 SW601.2
N115785370: length 2.2
  TOP w0.091: SW601.4 45.87,53.59 R602.2
N115785372: length 2.2
  TOP w0.091: SW601.6 45.8,52.32 R603.2
N115785374: length 2.3
  TOP w0.091: R604.2 45.72,51.05 SW601.8
N115788648: length 3.5
  TOP w0.091: R613.2 5.53,70.02 3.72,68.21 D601.A
N115837191: length 5.7
  TOP w0.081: U501.K5 104.24,40.15 102.38,40.15 101.87,39.64
  TOP w0.091: TP504.1 101.81,39.57 101.87,39.64
N115863629: length 3.9
  TOP w0.091: U1712.39 85.83,29.82 85.73,29.73 85.73,28.61 84.79,27.66 84.76,27.66 R508.1
N115865392: length 5.2
  TOP w0.081: 106.17,29.07 105.27,29.07 U1709.F2
  TOP w0.102: R1795.2 106.31,31.4 106.31,29.21 106.17,29.07
N115871876: length 29.9
  TOP w0.152: 105.98,30.59 105.98,29.46 105.84,29.32 U1709.G1
  TOP w0.203: R1203.2 99.53,18.94 96.46,22.01 96.46,30.06 101,34.6 104.63,34.6 106.16,33.07 106.16,31.87 105.98,31.69 105.98,30.59
N115938225: length 2.3
  TOP w0.076: v1(106.35,26.64) 105.93,27.07 105.28,27.07 U1709.C2
  TOP w0.203: v1(105.34,25.74) 105.34,25.81 105.02,26.13 U1709.A2
N115938370: length 3
  TOP w0.076: U1709.B4 103.77,26.58 103.77,25.87
  TOP w0.091: 104.01,25.15 104.01,25.09
  TOP w0.102: 103.77,25.87 103.77,25.39 104.01,25.15
  TOP w0.152: R1800.1 104.35,24.75 104.01,25.09
N115938505: length 10.8
  TOP w0.076: 102.29,28.08 102.61,28.08 102.87,27.82 U1709.D6
  TOP w0.081: 102.32,27.57 102.32,27.58 102.77,27.58 U1709.C6
  TOP w0.152: 102.29,28.08 102.17,28.2 102.02,28.2 ; v1(101.54,27.49) 101.62,27.57 102.32,27.57 ; U1709.G2 105.12,29.32 v1(105.58,29.78) ; U1709.G4 103.97,29.37 103.97,29.84 v1(103.82,29.99)
  TOP w0.203: 101.18,28.49 101.72,28.49 102.02,28.2
  TOP w0.254: L1201.2 100.79,27.03 101.06,27.03 101.51,27.49 v1(101.54,27.49)
  TOP w0.508: L1201.2 100.49,27.6 100.51,27.62 C1209.1 101.18,28.49
  BOTTOM w0.254: C1765.1 103.93,29.88 v1(103.82,29.99) ; C1207.1 106.35,29.78 v1(105.58,29.78)
N115954867: length 1.3
  TOP w0.203: R1798.1 102.33,20.43 C1769.2
N115954870: length 1.3
  TOP w0.203: R1801.1 105.71,20.29 C1770.2
N115959933: length 7.2
  TOP w0.076: U1709.C5 103.28,27.08 102.25,27.08 101.79,26.61 101.65,26.61
  TOP w0.152: 101.65,26.61 100.66,25.63 99.38,25.63 97.75,24 C1210.1
N115991118: length 11.5
  TOP w0.091: U904.12 131.99,24.62 R954.1 133.32,25.5 134.72,26.89 R1813.2 134.73,27.05 R953.2 135.58,26.06 135.24,25.72 Q902.3
N116057568: length 4.9
  TOP w0.081: 101.42,29.59 102.19,28.82 U1709.F7
  TOP w0.091: TP1953.1 99.85,30.86 100.78,30.86 101.22,30.43 101.22,29.79 101.42,29.59
N116084647: length 2.6
  TOP w0.091: U1713.5 12.11,49.92 R1718.1
N116084649: length 1.9
  TOP w0.091: U1713.8 9.57,49.92 8.91,50.58 R1723.1
N116084651: length 2.8
  TOP w0.091: U1713.4 11.87,49.31 12.71,50.15 R1717.1
N116084659: length 3.3
  TOP w0.091: U1713.9 8.96,49.31 7.8,50.46 R1724.1
N116084661: length 4.4
  TOP w0.091: U1713.1 11.61,48.11 12.51,47.2 12.51,45.91 13.12,45.3 R1719.1
N116086427: length 1.5
  TOP w0.091: R1817.2 10.78,46.19 U1713.15
N116086430: length 1.7
  TOP w0.091: R1818.2 10.38,46.85 U1713.14
N116086433: length 2.5
  TOP w0.091: U1713.13 9.98,47.24 9.7,46.96 8.89,46.96 8.51,46.59 R1819.2
N116086500: length 3.4
  TOP w0.091: R1820.2 7.54,46.05 9.6,48.11 U1713.12
N116087925: length 1.7
  TOP w0.091: U1713.16 11.18,46.66 R1821.1
N116088365: length 2.1
  TOP w0.091: R1720.1 11.61,50.52 11.02,50.52 10.78,50.28 U1713.6
N116088374: length 1.5
  TOP w0.091: U1713.7 10.38,50.42 R1721.1
N116165116: length 7.6
  TOP w0.091: R956.1 115.1,19.14 R957.1 115.43,19.14 115.62,18.94 115.62,17.34 117.6,15.36 J1707.64
N116167004: length 6.8
  BOTTOM w0.203: U1004.15 38.73,52.04 C1024.1
  BOTTOM w0.508: C1024.1 37.91,53.94 R1083.2 35.34,53.94 C1023.1
N116167167: length 1.4
  BOTTOM w0.381: R1072.1 42.16,55.43 D1012.C
N116167227: length 6.4
  BOTTOM w0.381: U1004.16 40.17,53.66 37.78,56.05 R1082.2 37.78,57.01 C1022.1
N116167406: length 2.5
  BOTTOM w0.203: R1077.2 43.97,52.54 U1004.1
N116167434: length 3
  BOTTOM w0.203: U1004.2 45.35,52.04 R1073.2 R1080.2
N116167436: length 17
  BOTTOM w0.203: R1081.2 35.46,46.97 36.43,46 44.9,46 45.47,46.57 R1074.2 45.01,48.92 45.01,50.04 44.52,50.54 U1004.5
N116167463: length 6.9
  BOTTOM w0.203: R1085.1 R1076.2 37.42,48.96 R1084.2 ; R1084.2 38.41,48.96 38.81,49.37 38.81,50.35 39,50.54 U1004.12 ; R1084.2 38.21,48.05 TP1020.1
N116167513: length 2.2
  BOTTOM w0.203: R1078.2 44.79,51.54 U1004.3
N116167550: length 2.8
  BOTTOM w0.203: U1004.4 44.49,51.04 45.47,50.05 R1079.2
N116167586: length 2.1
  BOTTOM w0.203: TP1015.1 43.57,47.02 U1004.8
N116167598: length 2.4
  BOTTOM w0.203: TP1016.1 40.17,47.46 U1004.9
N116167606: length 3.3
  BOTTOM w0.203: TP1017.1 39.47,46.91 39.47,49.29 39.73,49.54 U1004.10
N116167616: length 4.2
  BOTTOM w0.203: TP1018.1 39.14,47.67 39.14,49.5 39.68,50.04 U1004.11
N116227167: length 2.1
  TOP w0.091: J1710.1 124.84,71.31 R745.1
N116260997: length 6.8
  TOP w0.091: v1(117.07,73.24) 117.07,72.64 TP1954.1
  BOTTOM w0.091: U915.C1 116.36,76.91 R863.2 118.15,75.11 117.07,74.03 v1(117.07,73.24)
N116323997: length 18.2
  BOTTOM w0.381: D1011.C 47.14,60.13 44.67,62.59 40.64,62.59 36.2,58.15 36.2,56.09 37.33,54.96 R1083.1
N116421020: length 1
  TOP w0.081: v1(78.22,50.39) 78.22,50.19 U201.A8
  BOTTOM w0.081: v1(78.22,50.39) 78.23,50.41 R211.1
N116438273: length 3.8
  TOP w0.112: R719.2 68.27,24.51 66.11,26.67 U701.24
N116438275: length 4.1
  TOP w0.112: U701.25 66.51,26.65 67.85,25.31 68.19,25.31 68.98,24.51 R717.2
N116438398: length 5
  TOP w0.112: R713.1 70.34,25.21 69.31,26.23 67.77,26.23 67.31,26.69 U701.27
N116438407: length 4.7
  TOP w0.112: U701.26 66.91,26.64 67.77,25.79 68.93,25.79 69.7,25.02 R712.1
N116439658: length 2.6
  BOTTOM w0.305: U1714.4 98.43,77.17 R1824.1 99.4,77.19 R1825.2
N116441929: length 3.5
  TOP w0.381: v1(77.4,72.36) 77.04,71.99 TP45.1 76.51,71.97 R1827.2
  BOTTOM w0.381: v1(77.4,72.36) 77.18,72.58 U58.3
N116441950: length 4.5
  BOTTOM w0.305: C10.1 75.85,76.78 R14.1 77.18,76.76 U58.4 76.48,74.82 R16.2
N116479778: length 1.1
  TOP w0.081: v1(73.81,47.26) 73.81,47.29 U201.G11
  BOTTOM w0.081: v1(73.81,47.26) 73.73,47.17 R102.2
N116481485: length 6.4
  TOP w0.091: v1(117.55,24.58) 117.5,24.58 117.12,24.21 117.12,19.13 R930.1
  BOTTOM w0.091: U908.2 v1(117.55,24.58)
N116482975: length 5.9
  TOP w0.091: v1(117.5,24.05) 117.5,21.22 118.13,20.59 R931.1
  BOTTOM w0.091: U908.3 117.37,24.18 v1(117.5,24.05)
N116484883: length 4.4
  BOTTOM w0.305: R746.1 116.06,26.28 116.17,26.17 U908.12 ; R746.1 115.06,27.12 R744.1 ; R746.1 116.92,27.12 R743.2
N116485241: length 1.7
  BOTTOM w0.091: R432.2 114.82,24.18 U908.9
N116561239: length 1.5
  BOTTOM w0.091: U908.10 114.25,24.58 R433.2
N116562204: length 2.6
  BOTTOM w0.091: U908.8 115.22,23.78 113.66,22.23 R741.1
N116562207: length 1.7
  BOTTOM w0.091: R751.1 114.78,22.87 115.29,23.38 U908.7
N116562556: length 1.6
  BOTTOM w0.091: R742.1 118.35,23.66 117.24,23.66 117.12,23.78 U908.4
N116562559: length 1.8
  BOTTOM w0.091: U908.5 117.83,23.38 R752.1

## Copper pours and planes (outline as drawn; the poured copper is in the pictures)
GND on TOP: 88.94,51.43 90.04,51.43 90.1,51.37 90.1,51.1 89.96,50.96 89.82,50.96 89.71,50.85 89.71,50.61 89.59,50.5 88.98,50.5 88.86,50.62 88.86,51.35
GND on TOP: 76.03,33.32 77.96,33.32 78.28,33 78.28,25.38 78.07,25.17 76.07,25.17 75.91,25.34 75.91,33.19
GND on TOP: 133.5,33.89 134.75,33.89 134.96,33.68 134.96,31.94 134.87,31.85 133.77,31.85 133.43,32.19 133.43,33.82
GND on TOP: 84.51,81.63 85.04,81.63 85.78,80.89 85.78,77.95 85.36,77.54 84.66,77.54 84.33,77.87 84.33,81.44
GND on TOP: 61.47,22.43 64.93,22.43 65.09,22.27 65.09,19.78 64.36,19.05 64.36,18.58 64.25,18.46 62.99,18.46 61.39,16.87 61.39,14.82 60.93,14.35 47.84,14.35 47.32,14.87 47.32,19.19 47.79,19.66 54.8,19.66 55.51,18.94 61.01,18.94 61.27,19.2 61.27,22.23
GND on TOP: 34.02,30.67 37.18,30.67 37.92,29.93 37.92,24.86 35.82,22.75 31.71,22.75 31.43,23.03 21.38,23.03 21.32,23.09 21.32,24.94 21.56,25.18 32.98,25.18 33.8,26 33.8,30.45
GND on TOP: 25.87,16.31 27.22,16.31 27.28,16.25 27.28,16.02 27.25,15.99 26.74,15.99 26.57,15.82 26.57,14.47 26.54,14.44 26.54,14.44 26.48,14.38 26.48,13.45 26.6,13.34 28.32,13.34 28.43,13.23 28.43,12.22 27.81,11.6 24.79,11.6 24.59,11.81 24.59,12.83 24.95,13.2 25.43,13.2 25.86,13.63 25.86,15.07 26.16,15.36 26.16,15.87 26.03,16 25.78,16 25.67,16.11
GND on TOP: outline of 88 points within 0.51,0.51 139.19,86.05
GND on TOP: 50.25,32.29 53.32,32.29 53.74,31.87 53.74,29.01 52.28,27.56 46.78,27.56 46.13,26.9 46.13,26.03 45.92,25.82 45.26,25.82 45.01,26.07 45.01,27.57 45.28,27.83 45.28,35.26 44.81,35.72 44.11,35.72 43.96,35.87 43.96,38.95 44.2,39.18 47.27,39.18 47.95,38.5 47.95,36.37 47,35.42 47,33.42 47.97,32.45 47.97,30.72 48.16,30.53 49.57,30.53 49.9,30.86 49.9,31.94
GND on TOP: 47.9,25.03 48.96,25.03 49.16,24.83 49.16,23.61 49.05,23.5 47.94,23.5 47.82,23.62 47.82,24.94
GND on TOP: 64.02,41.47 67.41,41.47 67.72,41.15 67.72,38.76 67.43,38.46 64.23,38.46 63.97,38.72 63.97,41.42
GND on BOTTOM: 61.8,33.17 67.34,33.17 67.76,32.75 67.76,28.06 67.11,27.41 65.42,27.41 64.82,28.01 61.96,28.01 61.6,27.64 61.6,27.32 61.46,27.17 60.95,27.17 60.82,27.3 60.82,29.19 61.96,30.32 61.96,31.73 61.59,32.09 61.59,32.96
GND on BOTTOM: 64.04,41.74 66.81,41.74 67.26,41.29 67.26,37.62 66.87,37.23 64.94,37.23 64.43,37.75 64.43,39.82 63.87,40.37 63.87,41.58
GND on BOTTOM: 71.25,33.18 81.3,33.18 81.95,32.52 81.95,31.54 80.83,30.41 80.83,29.1 79.66,27.93 79.66,26.68 79.19,26.21 75.13,26.21 74.16,27.17 71.5,27.17 71.48,27.15 71.01,27.62 71.01,32.93
GND on BOTTOM: 121.56,12.1 132.55,12.1 134.14,10.5 134.14,6.98 133.39,6.22 126.4,6.22 124.53,4.35 108.71,4.35 108.17,4.89 108.17,6.51 108.66,7 113.09,7 114.85,8.76 120.23,8.76 121.03,9.56 121.03,11.57
GND on BOTTOM: 45.69,22.66 47.3,22.66 48.01,21.94 48.01,20.21 51.22,17 51.22,15.17 50.97,14.92 48.62,14.92 45.43,18.12 45.43,22.39
GND on BOTTOM: 104.18,23.91 109.12,23.91 110.09,24.88 110.6,24.88 110.93,24.55 110.93,21.71 110.53,21.31 110.2,21.31 109.88,20.98 105.31,20.98 103.94,22.36 103.94,23.67
GND on BOTTOM: 133.25,32.39 135,32.39 135.18,32.21 135.18,31.5 134.59,30.91 134.59,26.75 135.31,26.04 135.31,23.8 135.08,23.57 133.73,23.57 131.37,25.93 131.37,30.51
GND on BOTTOM: 0.51,86.05 139.19,86.05 139.19,0.51 105.27,0.51 105.15,0.62 105.15,1.52 104.96,1.71 101.84,1.71 101.59,1.47 101.59,0.68 101.42,0.51 0.51,0.51 ; 1 cut-out
GND on BOTTOM: 85.56,33.15 88.13,33.15 88.74,32.54 89.82,32.54 90.15,32.87 90.15,33.41 90.13,33.44 90.13,34.18 94.22,38.27 95.32,38.27 95.58,38.02 95.58,36.64 93.18,34.24 93.18,33.41 92.62,32.86 92.58,32.86 91.8,32.08 91.8,29.63 91.59,29.41 85.55,29.41 84.93,30.04 84.93,32.52
GND on L2_GND: 0.51,86.05 139.19,86.05 139.19,0.51 105.3,0.51 105.3,1.74 101.52,1.74 101.52,0.78 101.25,0.51 98.07,0.51 98.07,16.51 98.06,16.56 98.03,16.6 97.13,17.5 97.09,17.53 97.04,17.54 92.77,17.54 92.72,17.53 92.68,17.5 91.11,15.94 91.08,15.9 91.07,15.85 91.07,14.64 90.75,14.32 78.98,14.32 78.08,15.21 78.04,15.24 77.99,15.25 76.27,15.25 76.22,15.24 76.18,15.21 75.52,14.55 75.49,14.51 75.48,14.46 75.48,12.05 75.49,12.02 75.51,11.98 77.27,9.44 77.27,0.51 55.43,0.51 5.7,0.51 5.7,0.51 0.51,0.51
GND on L3_PWR: 0.51,86.05 139.19,86.05 139.19,85.14 14.7,85.14 13.52,83.96 13.52,81.1 12.71,80.29 7.88,80.29 6.83,79.24 6.83,71.47 1.45,66.09 1.45,11.14 11.86,11.14 15.9,15.18 25.41,15.18 25.58,15.36 27.48,15.36 27.52,15.31 28.65,15.31 31.74,12.22 31.74,9.37 31.7,9.33 31.7,8.96 32.89,7.77 36.28,7.77 38.56,5.5 48.36,5.5 49.19,4.66 49.19,1.35 48.92,1.07 48.92,0.51 0.51,0.51
GND on L3_PWR: 85.84,65.77 92.1,65.77 92.83,65.04 92.83,62.13 92.53,61.84 90.28,61.84 89.91,61.47 89.91,59.2 88.65,57.93 88.08,57.93 87.21,58.81 85.14,58.81 84.99,58.96 84.99,64.92
GND on L3_PWR: 138.61,6.19 139.19,6.19 139.19,0.51 106.91,0.51 106.91,1.15 107.09,1.33 110.86,1.33 111.85,2.31 111.85,4.09 112.17,4.41 129.76,4.41 131.2,2.97 135.39,2.97
GND_CHASSIS on TOP: 93.49,17.8 97.31,17.8 97.68,17.44 97.68,13.29 98.12,12.84 98.12,1.57 97.68,1.13 77.99,1.13 77.19,1.93 77.19,10.7 75.56,12.33 75.56,14.91 75.84,15.19 77.81,15.19 79.87,13.14 90.04,13.14 91.37,14.47 91.37,15.68
GND_CHASSIS on BOTTOM: 78.5,13.21 95.77,13.21 98.16,10.82 98.16,1.78 97.43,1.04 78.37,1.04 77.5,1.91 77.5,12.21
GND_CHASSIS on L2_GND: 92.82,17.29 96.99,17.29 97.82,16.46 97.82,0.51 77.53,0.51 77.53,9.48 77.52,9.52 77.51,9.55 75.74,12.09 75.74,14.41 76.32,15 77.94,15 79.12,13.82 90.45,13.82 91.33,14.7 91.33,15.79
VBUS_IN on TOP: 47.24,13.45 60.55,13.45 61.68,12.32 61.68,7.49 63.18,5.99 63.18,3.36 62.98,3.16 61.23,3.16 60.35,4.04 60.35,7.69 59.17,8.87 46.7,8.87 43.61,11.97 43.61,19.03 41.36,21.28 41.36,22.41 38.56,25.21 38.56,30.58 38,31.15 38,32.27 38.65,32.93 38.65,34.74 38.76,34.84 39.04,34.84 39.17,34.71 39.17,32.64 39.96,31.85 40.78,31.85 41.99,30.64 43.24,30.64 43.6,31.01 44.75,31.01 44.91,30.85 44.91,29.7 44.9,29.69 44.9,28.1 44.75,27.95 44.75,25.55 44.58,25.38 44.58,21.86 44.83,21.61 44.83,20.52 46.32,19.03 46.32,14.37
VBUS_IN on TOP: 21.65,22.5 24.44,22.5 24.65,22.29 24.65,20.43 24.08,19.87 23.54,19.87 23.03,19.37 23.03,15.69 22.84,15.49 21.98,15.49 21.4,16.07 21.4,22.24
VBUS_IN on BOTTOM: 41.43,22.83 43.9,22.83 44.13,22.6 44.13,19.88 43.83,19.58 42.69,19.58 41.1,21.18 41.1,22.49
VBUS_IN on L3_PWR: 35.4,19.18 37.54,19.18 40.91,22.55 42.59,22.55 43.2,21.93 43.2,16.73 42.26,15.79 33.26,15.79 32.8,16.24 32.8,22.04 32.33,22.52 29.64,22.52 29.11,21.99 29.11,17.52 27.38,15.79 21.79,15.79 21.15,16.43 21.15,20.51 21.99,21.35 21.99,24.43 23.9,26.34 34.58,26.34 35.01,25.92 35.01,23.53 34.98,23.51 34.98,19.59
VCC_FT_3V3 on L3_PWR: 5.35,69.41 13.22,69.41 18.83,63.8 18.83,38.12 20.2,36.76 20.2,22.4 17.14,19.34 17.14,16.94 11.93,11.73 2.02,11.73 1.69,12.06 1.69,65.75
VDD_1V8 on TOP: 89.89,52.46 90.15,52.46 90.24,52.37 90.24,51.73 90.04,51.53 88.93,51.53 88.79,51.39 88.79,50.86 88.43,50.5 87.33,50.5 87.28,50.55 87.28,50.84 87.38,50.94 88.01,50.94 88.23,51.17 88.23,51.75 88.34,51.86 89.65,51.86 89.77,51.97 89.77,52.34
VDD_1V8 on TOP: 60.47,57.11 66.88,57.11 67.74,56.25 67.74,55.59 67.63,55.47 67.33,55.47 66.95,55.86 66.95,56.02 66.6,56.36 64.06,56.36 63.64,55.95 63.64,46.69 64.17,46.16 66.73,46.16 67.28,46.7 67.28,46.99 67.29,47 67.81,47 67.81,46.61 67.8,46.61 68.2,46.21 74.13,46.21 74.49,46.56 74.49,46.96 74.63,47.11 74.79,47.11 74.99,46.91 74.99,45.73 74.63,45.37 73.34,45.37 73,45.71 61,45.71 59.28,47.44 59.28,55.92
VDD_1V8 on TOP: 59.79,25.01 60.9,25.01 60.95,24.96 60.95,19.32 60.86,19.23 56.96,19.23 56.77,19.42 56.77,22.83 57.27,23.32 59.12,23.32 59.68,23.88 59.68,24.9
VDD_1V8 on BOTTOM: 88.04,51.67 89.08,51.67 89.2,51.55 89.2,51.36 89.04,51.2 88.79,51.2 88.68,51.09 88.72,51.05 88.72,50.13 88.83,50.02 88.83,45.76 87.67,44.59 85.82,44.59 83.96,42.73 74.48,42.73 74.45,42.75 73.54,42.75 72.69,43.6 72.69,48.1 73.23,48.64 73.79,48.64 74.15,49.01 74.43,49.01 74.64,48.79 74.64,48.29 74.63,48.28 74.63,47.82 74.93,47.52 74.93,46.32 75.16,46.09 78.55,46.09 80.36,44.27 82.33,44.27 83.75,45.69 85.85,45.69 86.64,46.48 86.64,48.7 87.78,49.84 87.78,51.41
VDD_1V8 on BOTTOM: 98.51,45.03 104.32,45.03 105.59,43.76 105.59,42.79 105.57,42.76 102.86,42.76 102.6,42.51 102.6,39.22 103.51,38.31 105.32,38.31 105.91,37.72 105.91,36.61 105.34,36.04 99.32,36.04 96.43,38.93 96.43,42.95
VDD_1V8 on BOTTOM: 117.3,31.1 125.02,31.1 127.7,28.43 127.7,23 127.06,22.36 123.4,22.36 120.88,24.88 119.02,24.88 118.85,24.71 116.78,24.71 116.56,24.93 116.56,26.51 116.63,26.58 116.43,26.79 114.63,26.79 114.47,26.94 114.47,30.2 115.25,30.97 117.17,30.97
VDD_1V8 on BOTTOM: 57.24,73.9 59.87,73.9 61.3,72.47 61.3,45.48 60.83,45.01 56.79,45.01 56.39,45.42 56.39,55.04 56.52,55.17 56.52,73.17
VDD_1V8 on L3_PWR: 97.2,43.37 97.2,35.03 86.64,24.47 56.88,24.47 56.16,23.76 56.16,20.87 57,20.03 62.64,20.03 62.75,20.15 78.61,20.15 80.38,18.38 91.76,18.38 92.7,19.32 92.7,23.6 94.79,25.69 97.44,25.69 97.6,25.54 97.8,25.54 98.33,25.01 100.02,25.01 101.63,26.61 101.82,26.61 103.84,28.64 103.84,29.42 104.02,29.6 104.02,30.34 104.17,30.49 105.27,30.49 105.42,30.34 105.42,29.45 105.47,29.41 105.47,28.72 105.89,28.29 119.17,28.29 119.78,28.9 119.78,30.77 117.73,32.83 110.16,32.83 101.21,41.78 101.21,43.28 100.68,43.81 97.64,43.81
VDD_1V8 on L3_PWR: 14.35,84.43 136.68,84.43 138.93,82.18 138.93,6.93 135.19,3.18 131.35,3.18 130.41,4.13 130.41,14.72 124.63,20.5 124.63,25.54 124.98,25.89 129.57,25.89 131.22,27.54 131.22,66.39 131.25,66.43 131.25,72.21 127.19,76.28 91.01,76.28 87.56,79.73 63.34,79.73 60.15,76.54 60.15,70.74 58.76,69.36 54.44,69.36 50.28,65.19 47.97,65.19 47.5,65.66 47.5,66.91 48.32,67.73 48.41,67.73 48.8,68.12 48.8,73.08 43.41,78.48 16.66,78.48 16.58,78.57 14.79,78.57 13.93,79.43 13.93,84.01
VDD_3V3 on TOP: 65.33,24.92 65.33,22.98 65.4,22.91 65.4,19.42 65.07,19.09 64.82,19.09 64.62,18.89 64.62,18.44 66.44,18.44 67.81,19.81 67.81,20.63 67.64,20.79 67.31,20.79 67.11,20.99 67.11,22.66 66.84,22.93 66.85,22.94 66.85,24.95 66.62,25.18 66.59,25.18 65.59,26.18 65.4,26.18 65.34,26.12 65.34,24.93
VDD_3V3 on TOP: 10.76,80.22 11.78,80.22 12.08,79.91 14.07,79.91 14.43,79.55 14.43,77.98 14.22,77.76 12.95,77.76 12.67,77.49 11.64,77.49 11.59,77.54 11.59,79.07 11.32,79.34 10.82,79.34 10.64,79.52 10.64,80.1
VDD_3V3 on BOTTOM: 95.63,62.79 96.29,62.79 96.44,62.64 96.44,61.83 96.18,61.56 96.18,57.97 96.11,57.9 96.11,57.29 95.46,56.64 95.46,55.5 92.55,52.59 90.46,52.59 90.34,52.72 90.34,53.05 90.79,53.5 91.7,53.5 92.59,54.4 92.59,55.33 93.54,56.28 93.54,57 94.63,58.09 95.36,58.09 95.52,58.25 95.52,62.68
VDD_3V3 on BOTTOM: 94.74,47.41 107.93,47.41 109.56,45.78 109.56,39.03 108.92,38.4 105.91,38.4 103.56,40.75 103.56,42.13 103.85,42.42 106.36,42.42 106.4,42.47 106.4,44.23 105.36,45.27 98.19,45.27 94.22,41.3 92.38,41.3 92.38,41.3 88.05,41.3 87.29,40.54 87.29,37.65 86.55,36.91 82.75,36.91 82.18,37.48 82.18,40.69 82.21,40.72 82.21,41.19 82.66,41.64 86.78,41.64 92.19,47.05 94.37,47.05
VDD_3V3 on BOTTOM: 90.24,61.55 90.82,61.55 90.89,61.47 90.89,58.72 89.29,57.11 89.29,54.71 89.08,54.51 88.33,54.51 88.21,54.64 88.21,54.89 88.4,55.08 88.48,55.08 88.62,55.23 88.62,57.5 90.1,58.97 90.1,61.41
VDD_3V3 on BOTTOM: 102.92,72.12 105.47,72.12 106.57,71.01 106.57,63.34 107.27,62.64 107.27,59.77 106.72,59.22 102.45,59.22 101.35,60.33 101.35,70.55
VDD_3V3 on L3_PWR: outline of 82 points within 7.21,4.53 130.74,79.89 ; 2 cut-outs
VDD_5V on TOP: 32.12,79.97 37.97,79.97 38.67,79.27 38.67,77.88 39.85,76.7 41.22,76.7 41.47,76.45 41.47,75.27 41.26,75.05 38.55,75.05 35,78.61 32.26,78.61 31.86,79.01 31.86,79.71
VDD_5V on TOP: 22.61,35.88 24.68,35.88 24.79,35.77 24.79,33.83 24.52,33.55 22.59,33.55 22.43,33.71 22.43,35.7
VDD_5V on TOP: 51.46,38.42 52.63,38.42 52.76,38.28 52.76,37.47 52.3,37.01 52.3,35.36 52.97,34.69 52.97,33.55 52.33,32.91 49.26,32.91 49.22,32.95 48.03,32.95 47.31,33.67 47.31,35.3 47.41,35.4 49.75,35.4 50.1,35.05 50.68,35.05 51.05,35.42 51.05,36.59 51.38,36.92 51.38,38.34
VDD_5V on BOTTOM: 29.99,77.73 29.79,77.92 29.79,78.7 30.88,79.78 33.68,79.78 33.93,79.53 33.93,77.95 33.71,77.73
VDD_5V on BOTTOM: 39.14,79.26 63.15,79.26 65.14,81.25 80.04,81.25 81.46,79.84 81.46,75.85 81.06,75.45 80.36,75.45 79.91,75.01 78.3,75.01 77.99,75.32 77.99,77.88 77.5,78.37 75.76,78.37 75.27,77.89 75.27,77.18 74.98,76.89 44.82,76.89 42.44,74.5 39.1,74.5 38.67,74.93 38.67,78.79
VDD_5V on BOTTOM: 23.45,35.62 25.01,35.62 25.19,35.43 25.19,34.01 24.87,33.69 23.26,33.69 23.02,33.93 23.02,35.19
VDD_5V on L3_PWR: 48.26,33.46 44.48,29.68 41.19,29.68 37.17,25.66 37.17,19.91 36.7,19.44 35.94,19.44 35.93,19.45 35.59,19.45 35.39,19.66 35.39,25.93 34.48,26.84 30.46,26.84 29.94,27.35 29.94,31.37 28.69,32.63 24.02,32.63 23.07,33.58 23.07,37.04 24.65,38.62 47.25,38.62 48.26,37.61
VDD_ANA_0V8 on L3_PWR: 80.03,62.36 80.82,61.57 82.88,61.57 83.99,60.46 83.99,58.4 84.36,58.02 84.71,58.02 84.71,57.93 86.35,56.29 86.35,56.1 85.8,55.55 85.45,55.55 85.27,55.73 83.4,55.73 78.57,60.56 62.93,60.56 59.83,57.46 59.83,37.39 60.28,36.94 60.28,36.73 67.77,36.73 72.13,32.37 86.06,32.37 92.49,38.8 92.49,50.4 91.88,51.01 90.64,51.01 90.26,51.39 90.26,51.95 90.52,52.22 90.52,53.22 90.23,53.51 90.23,53.76 90.38,53.91 90.73,53.91 91.28,53.36 93.63,53.36 93.91,53.07 93.97,53.07 94.9,52.15 94.9,48.38 95.95,47.32 95.95,45.63 94.9,44.57 94.9,37.78 86.11,28.99 71.7,28.99 67.58,33.11 56.69,33.11 56.14,33.65 56.14,34.92 56.19,34.96 56.19,57.51 62.02,63.35 79.04,63.35
VDD_ANA_1V8 on BOTTOM: 55.91,21.3 58.23,21.3 58.41,21.12 59.11,21.12 59.49,21.5 59.49,21.97 59.59,22.07 60.4,22.07 60.55,21.92 60.55,21.03 58.7,19.17 56.11,19.17 55.73,19.54 55.73,21.12
VDD_ANA_1V8 on L3_PWR: 86.06,28.51 95.08,37.54 95.08,44.4 96.18,45.5 96.18,47.51 95.08,48.6 95.08,52.45 93.96,53.57 90.32,53.57 90.22,53.66 90.22,53.9 90.18,53.86 90.18,53.58 90.35,53.42 90.35,52.18 90.11,51.95 89.92,51.95 89.78,52.09 89.78,52.74 89.16,53.36 87.79,53.36 87.14,52.71 87.14,52.42 87.21,52.35 87.21,52.05 87.11,51.95 86.86,51.95 86.77,52.04 86.77,53.75 86.83,53.82 86.88,53.82 86.88,55 87.04,55.16 87.46,55.16 87.62,55 87.62,54.86 88.12,54.37 89.59,54.37 89.63,54.41 89.63,56.03 90.13,56.53 90.88,56.53 90.91,56.5 94.94,56.5 95.05,56.39 95.07,56.41 97.4,56.41 98.1,55.72 98.1,44.94 96.81,43.65 96.81,35.05 86.55,24.79 55.39,24.79 54.05,26.13 54.05,32.03 54.69,32.67 67.1,32.67 71.25,28.51
VDD_SOC_0V85 on TOP: 76.36,33.7 76.09,33.7 75.63,33.25 75.63,29.68 75.48,29.52 74.59,29.52 74.37,29.74 74.37,30.22 73.76,30.83 72.5,30.83 72.35,30.98 72.35,33.32 72.59,33.56 73.49,33.56 73.73,33.79 73.73,34.76 73.84,34.87 73.94,34.87 73.94,36.82 74.28,37.15 75.17,37.15 75.37,37.35 75.37,37.96 75.36,37.97 75.51,38.12 76.84,38.12 76.97,37.99 76.97,34.31
VDD_SOC_0V85 on TOP: 88.34,54.42 88.65,54.42 88.76,54.31 88.76,54.09 88.96,53.89 89.58,53.89 89.67,53.8 89.67,51.92 87.37,51.92 87.29,52 87.29,53.81 87.33,53.85 88.09,53.85 88.26,54.02 88.26,54.34
VDD_SOC_0V85 on L3_PWR: 89.84,52.98 89.84,51.92 90.13,51.64 90.13,51.07 90.21,50.99 90.21,41.79 84.27,35.85 74.69,35.85 74.22,36.32 74.22,38.3 75.14,39.22 76.96,39.22 86.84,49.1 86.84,51.9 87,52.06 87,52.76 87.45,53.21 89.61,53.21
DCIN_15V on TOP: 57.03,4.27 58.96,4.27 60.28,2.94 63,2.94 63.28,2.65 63.28,1.18 63,0.9 61.36,0.9 61.08,1.19 56.8,1.19 56.59,1.4 56.59,3.82
ETH1_VDDIO on BOTTOM: 88.03,41.03 92.86,41.03 93.92,39.98 93.92,38.77 89.62,34.47 89.62,33.04 89.37,32.79 89.06,32.79 88.48,33.37 87.81,33.37 87.55,33.62 87.55,34.2 86.96,34.79 85.89,34.79 85.75,34.93 85.75,35.51 86.18,35.93 86.33,35.93 87.55,37.15 87.55,40.55
EXP_3V3 on TOP: 82.57,78.82 83.72,78.82 83.97,78.57 83.97,76.22 83.88,76.14 82.6,76.14 82.11,76.63 82.11,78.36
EXP_5V on TOP: 82.02,83.26 83.64,83.26 83.95,82.95 83.95,79.71 83.72,79.48 82.33,79.48 81.7,80.11 81.7,82.94
EXP_5V on BOTTOM: 83.02,81.31 83.9,81.31 84.2,81 84.2,78.88 83.05,77.72 83.05,72.7 82.8,72.45 78.98,72.45 78.76,72.68 78.76,73.68 79.23,74.16 80.83,74.16 81.69,75.02 81.69,78.29 82.39,78.99 82.39,80.68
LPD4/X_VDD2_1V1 on TOP: 63.15,41.74 63.59,41.3 63.59,35.97 63.57,35.95 62.64,35.95 62.42,36.18 62.42,38.63 60.26,40.79 60.26,44.22 60.49,44.46 62.71,44.46 63.16,44.01 63.16,43.86 63.15,43.85
LPD4/X_VDD2_1V1 on TOP: 86.34,52.96 86.61,52.96 86.7,52.87 86.7,51.02 86.86,50.86 87.1,50.86 87.13,50.83 87.13,50.6 87.02,50.49 86.27,50.49 86.13,50.35 86.13,50.12 86.04,50.03 85.89,50.03 85.77,50.16 85.77,50.92 85.88,51.04 86.12,51.04 86.27,51.19 86.27,52.89
LPD4/X_VDD2_1V1 on BOTTOM: 86.35,53.39 86.63,53.39 86.7,53.33 86.7,52.1 87.11,51.69 87.11,50.32 86.89,50.11 85.81,50.11 85.61,50.31 85.61,50.6 85.27,50.94 83.8,50.94 83.57,51.18 83.57,51.5 83.86,51.8 85.51,51.8 85.81,52.1 85.81,52.37 85.99,52.55 86.01,52.55 86.3,52.84 86.3,53.34
LPD4/X_VDD2_1V1 on L3_PWR: 86.71,54.78 86.71,49.49 76.84,39.62 60.77,39.62 60.26,40.14 60.26,57.4 63.2,60.35 78.28,60.35 83.29,55.34 85.43,55.34 85.45,55.32 86.17,55.32
LPD4/X_VDDQ_0V6 on TOP: 63.79,44.87 67.41,44.87 68.07,44.21 68.07,41.94 67.9,41.77 63.78,41.77 63.51,42.04 63.51,44.59
LPD4/X_VDDQ_0V6 on BOTTOM: 71.34,51.74 74.01,51.74 74.79,52.52 74.79,53.72 74.89,53.83 75.22,53.83 75.39,53.66 75.39,53.44 75.49,53.33 76.51,53.33 76.76,53.58 76.76,53.72 76.92,53.89 77.62,53.89 77.92,53.58 77.92,49.05 77.36,48.49 76.91,48.49 76.76,48.64 76.76,48.88 76.5,49.14 75.62,49.14 75.47,48.98 75.47,48.51 75.26,48.31 74.89,48.31 74.73,48.46 74.73,49.09 73.76,50.07 69.36,50.07 68.91,50.51 67.72,50.51 67.54,50.33 67.54,42.55 67.28,42.29 62.26,42.29 61.76,42.8 61.76,59.22 63.86,61.32 81.8,61.32 83.8,59.33 83.8,58.25 84.48,57.57 84.48,57.55 85.11,56.92 85.11,55.68 85.41,55.38 85.9,55.38 86.31,54.97 86.49,54.97 86.75,54.71 86.75,54.09 86.87,53.97 87.17,53.97 87.17,53.69 87.06,53.58 87.06,53.48 86.31,53.48 86.02,53.77 85.25,53.77 85.05,53.96 84.54,53.96 84.36,54.14 84.36,54.32 84.02,54.66 83.46,54.66 81.15,56.97 81.15,57.02 80.1,58.06 68.81,58.06 67.91,57.16 67.91,53.11 68.27,52.74 70.34,52.74
